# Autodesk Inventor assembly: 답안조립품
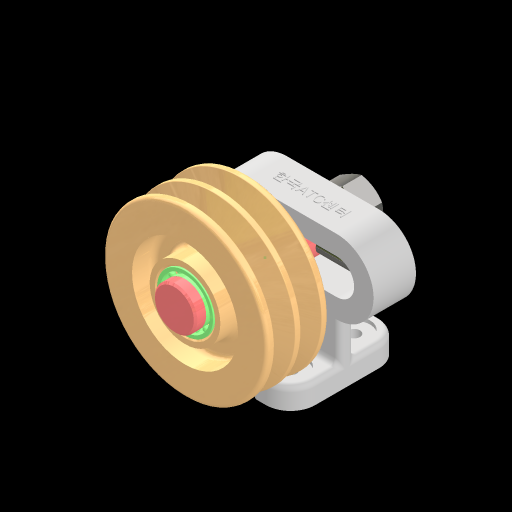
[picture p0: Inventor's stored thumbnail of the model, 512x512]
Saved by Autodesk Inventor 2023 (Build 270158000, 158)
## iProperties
Created: 2025-01
Part Number: 답안조립품
Document SubType Name: Assembly
Designer: 강의실01
Author: 강의실01
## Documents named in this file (9)
- C:\Users\kimgi\Desktop\750103V1004\답안조립품.iam
- C:\Users\kimgi\Desktop\750103V1004\본체.ipt
- C:\Users\kimgi\Desktop\750103V1004\축.ipt
- C:\Users\kimgi\Desktop\750103V1004\스프링 와셔 M16.ipt
- C:\Users\kimgi\Desktop\750103V1004\육각 너트 M16.ipt
- C:\Users\kimgi\Desktop\750103V1004\평 와셔 M16.ipt
- C:\Users\kimgi\Desktop\750103V1004\육각 머리 볼트 M8x80.ipt
- C:\Users\kimgi\Desktop\750103V1004\V-벨트 풀리.ipt
- C:\Users\kimgi\Desktop\750103V1004\깊은 홈 볼 베어링 6804.ipt
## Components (1 placed, 1 different names)
1. V-벨트 풀리:1
